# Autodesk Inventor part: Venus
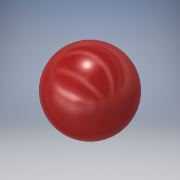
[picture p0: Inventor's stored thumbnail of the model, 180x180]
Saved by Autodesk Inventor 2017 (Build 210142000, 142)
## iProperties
Created: 2016-07
Part Number: Venus
Material: Generic
Document SubType Name: Modeling
Designer: Stan
Density: 1 g/cm^3
Appearance: Red
Author: Stan
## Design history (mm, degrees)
sketch "Sketch1"
  geometry: L1 (0, 12.7)-(0, -12.297); L2 (-3.175, -12.297)-(0, -12.297); A1 r 12.7 centre (0, 0) between (0, 12.7) and (-3.175, -12.297); 1 further point
  constraints: 4 end point, 2 point on circle, 1 centre point, 1 coincident, 1 perpendicular, 1 vertical
  dimensions: "d0" = 25.4 diameter of A1; "d2" = 3.175 distance of L2.start L1.end
revolve "Revolution1" sketch "Sketch1" stored, may be unused: angle "d3" = 90 deg
sketch "Sketch2"
  geometry: C1 r 1.587 at (0, 0); 1 further point
  constraints: 1 centre point, 1 coincident
  dimensions: "d4" = 3.175 diameter of C1
extrude "Extrusion1" cut sketch "Sketch2" distance "d5" = 6.35; taper "d6" = 0 deg
body "Solid1"
